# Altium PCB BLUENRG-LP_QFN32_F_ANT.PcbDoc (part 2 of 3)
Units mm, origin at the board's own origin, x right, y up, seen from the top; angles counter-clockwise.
Board outline 90.84 x 54.03 mm, 4 copper layers (Top Layer, G1 Layer, G2 Layer, Bottom Layer), stack 1.697 mm thick; 142 components, 101 nets, 450 pads, 662 vias.
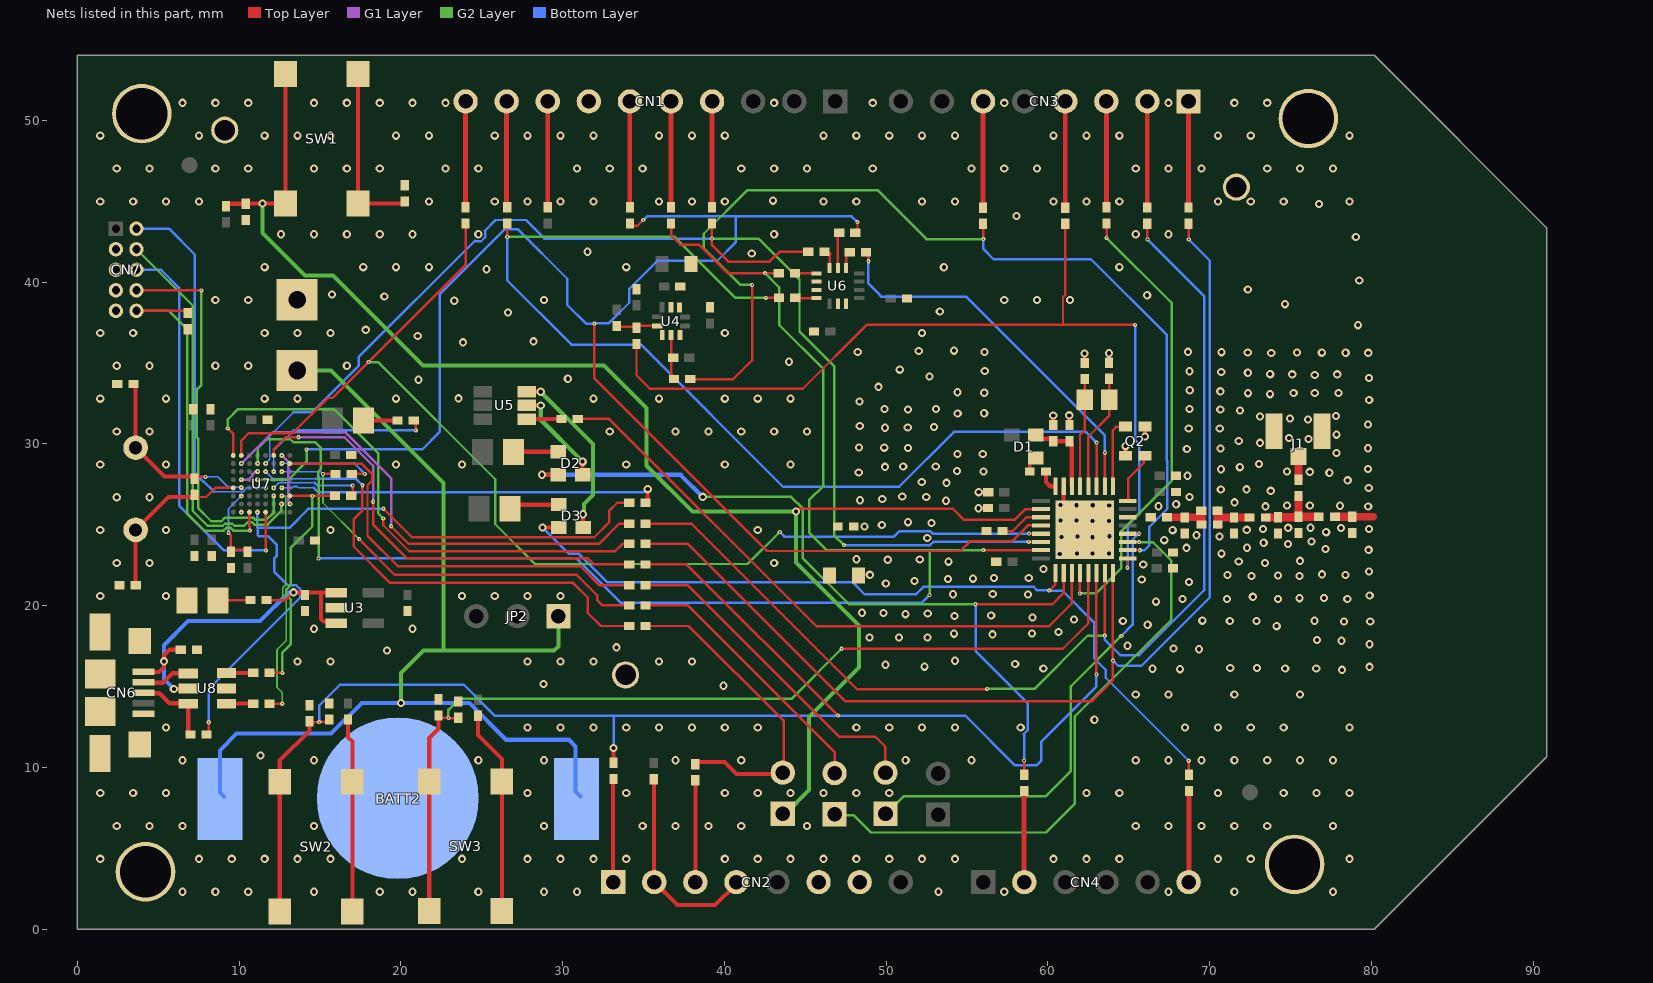
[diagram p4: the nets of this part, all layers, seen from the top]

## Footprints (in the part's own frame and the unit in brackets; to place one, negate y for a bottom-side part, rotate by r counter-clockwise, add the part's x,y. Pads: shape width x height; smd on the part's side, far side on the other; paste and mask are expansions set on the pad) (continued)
UFL_SMT [mm]
  rect 1.05x2.2 smd: 1(0.65,0.4) 3(3.6,0.4)
  rect 1x1.05 smd: 2(2.15,-1.15)
  silkscreen extent 0.1,-1.7 4.15,1.55, body extent 0.12,-1.67 4.13,1.5, height 0.76

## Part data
BATT2: library part "Battery holder_0"
C1 C2 C3 C4 C5 C6 C7 C8 C9 C10 C11 C12 C13 C14 C15 C16 C17 C19 C27 C28 C30 C31 C32 C33 C34 C35 C36 C39 C42 C43 C44: library part "MURATA GRM36"
C20 C21 C22 C23 C24 C25 C26 C29 C40 C41: library part C, PSpiceTemplate="C^@REFDES %1 %2 ?TOLERANCE[]C^@REFDES[] @VALUE ?IC/IC{}@IC/ ?TOLERANCE[]\n.model C^@REFDES CAP C{}1 DEV{}@TOLERANCE%[]"
CN6: library part "USB micro B_0"
CN7: library part CON10AP
D1 D2 D3: library part DEV3L_0
DL3 DL4: library part Diodo_led
J1: "50 Ohms, SMA Jack Receptacle, Edge Mount, .25µm Gold (Au) Plating", Manufacturer=Molex
JP1 JP3 JP4 JP5: library part Buzzer
L1 L2 L3 L4 L5 L6: library part IND_short
Q1: library part QUARZO
Q2: library part NX3225SA
R1 R2 R3 R4 R5 R6 R7 R8 R9 R13 R17 R18 R20 R22 R24 R25 R26 R27 R28 R30 R31 R32 R33 R35 R37 R38 R39 R41 R42 R43 R44 R45 R46 R47 R48 R49 R52 R53 R54 R55 R56 R57 R58 R59 R60 R61: library part R_Dup1, PSpiceTemplate="R^@REFDES %1 %2 ?TOLERANCE[]R^@REFDES[] @VALUE  ?TOLERANCE[]\n.model R^@REFDES RES R{}1 DEV{}@TOLERANCE%[]"
R29 R34 R36 R40: library part R
ST1: library part STlogo
SW1 SW2 SW3: library part SWITCH-1
TP1 TP2 TP3: library part "T POINT R"
U3: "LDLN025 Series 3.3 V 250 mA Surface Mount Fixed Ultra Low Noise LDO - SOT-23-5L", Package="SOT-23-5 STMicroelectronics"
U4: library part LPS25HB
U7: library part STM32F10XRXY, "No Description Available"
U8: library part USBUFxxW6_0
X1: library part QUARZO_Dup1

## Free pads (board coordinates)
  rect 0.254x1.092 smd: 1(60.471,22.025) 2(60.979,22.025) 3(61.487,22.025) 4(61.995,22.025) 5(62.503,22.025) 6(63.011,22.025) 7(63.519,22.027) 8(64.027,22.025) 17(64.027,27.384) 18(63.519,27.384) 19(63.011,27.384) 20(62.503,27.384) 21(61.995,27.384) 22(61.487,27.384) 23(60.979,27.384) 24(60.471,27.384)
  rect 1.092x0.254 smd: 9(64.929,22.926) 10(64.929,23.434) 11(64.929,23.942) 12(64.929,24.45) 13(64.929,24.958) 14(64.929,25.466) 15(64.929,25.974) 16(64.929,26.482) 25(59.57,26.482) 26(59.57,25.974) 27(59.57,25.466) 28(59.57,24.958) 29(59.57,24.45) 30(59.57,23.942) 31(59.57,23.434) 32(59.57,22.926)
  rect 3.607x3.607 smd: 33(62.275,24.704)

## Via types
v1: diameter 0.508, hole 0.254, Top Layer to Bottom Layer, tented both sides, 569 vias
v2: diameter 0.254, hole 0.102, Top Layer to Bottom Layer, tented both sides, 93 vias

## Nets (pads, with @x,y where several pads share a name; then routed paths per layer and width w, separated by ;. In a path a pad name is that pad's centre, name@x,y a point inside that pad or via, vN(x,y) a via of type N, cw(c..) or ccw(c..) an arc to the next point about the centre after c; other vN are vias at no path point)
BLE_RSTN: C20.2 JP5.1 pad.26 R26.2 SW1.3 SW1.4 | length 93.8
  Top Layer w0.102: R26.2@9.195,44.831 R26.2@9.212,44.848 ; C20.2@10.414,44.848 C20.2@10.422,44.856 ; SW1.4@12.866,44.856 SW1.4@12.867,44.858
  Top Layer w0.152: v1(44.422,25.822) 44.607,26.007 54.117,26.007 54.822,25.301 57.93,25.301 58.604,25.976 pad.26@59.508,25.976
  Top Layer w0.254: R26.2@9.212,44.848 C20.2@10.414,44.848 ; C20.2@10.422,44.856 v1(11.455,44.856) ; v1@11.457,44.858 11.459,44.856 SW1.4@12.866,44.856 ; SW1.4@12.867,44.858 SW1.3@12.867,52.868
  G2 Layer w0.254: v1(11.455,44.856) 11.455,43.029 14.073,40.411 15.809,40.411 21.364,34.856 32.555,34.856 35.189,32.222 35.189,28.651 38.019,25.822 v1(44.422,25.822) 44.422,22.68 48.316,18.786 48.316,16.187 45.242,13.114 45.242,8.616 JP5.1@43.675,7.048
  Bottom Layer w0.152: v1(44.422,25.822) v1@44.433,25.833
BLE_SWCLK: JP3.1 pad.12 | length 29.7
  Top Layer w0.102: pad.12@64.918,24.45 v2@65.571,24.45
  G2 Layer w0.152: JP3.1@49.949,7.074 51.084,8.209 59.855,8.209 61.417,9.771 61.417,15.021 64.519,18.123 v2(64.534,18.123)
  Bottom Layer w0.152: v2@64.534,18.138 v2(64.534,18.123) 65.241,18.83 65.241,24.079 65.608,24.445 v2(65.635,24.445)
BLE_SWDIO: JP4.1 pad.11 | length 36.6
  Top Layer w0.102: pad.11@64.985,23.937 v2@65.638,23.937
  Top Layer w0.152: pad.11@64.98,23.942 pad.11@64.985,23.937 ; v2@65.638,23.937 v2(65.643,23.933)
  G2 Layer w0.152: JP4.1@46.838,7.036 48.006,7.036 49.06,5.982 59.873,5.982 61.671,7.78 61.671,13.167 67.635,19.131 67.635,22.778 66.481,23.933 v2(65.643,23.933)
BOOT0: CN7.10 R58.2 U7.A6 | length 23.8
  Top Layer w0.152: CN7.10@3.658,38.227 R58.2@6.833,38.227 ; U7.A6@10.643,25.786 10.643,24.919 10.668,24.894 v2(10.668,24.638)
  G2 Layer w0.152: CN7.10@3.658,38.227 5.664,38.227 6.807,37.084 6.807,25.679 7.849,24.638 9.043,24.638 9.221,24.816 9.473,24.816 9.651,24.638 v2(10.668,24.638)
DM: CN6.2 U8.4 | length 2.9
  Top Layer w0.254: CN6.2@4.293,15.24 5.309,15.24 5.893,15.824 6.706,15.824 U8.4@6.853,15.677
DP: CN6.3 R43.2 U8.6 | length 4.7
  Top Layer w0.254: CN6.3@4.293,14.59 5.069,14.59 5.69,13.97 6.701,13.97 6.858,13.813 R43.2@6.858,12.04
DP-CON: R43.1 R59.2 U7.A5 | length 43.3
  Top Layer w0.152: v2@8.125,12.802 v2(8.128,12.799) R43.1@8.128,12.04 ; v2(18.92,25.997) 20.686,24.232 31.954,24.232 32.872,25.149 32.872,25.861 33.376,26.365 R59.2@33.985,26.365
  Bottom Layer w0.152: v2(8.128,12.799) 8.128,14.859 13.792,20.523 13.792,21.007 13.539,21.26 13.03,21.26 12.167,22.123 12.167,22.911 12.319,23.063 12.319,23.774 11.811,24.282 11.237,24.282 11.148,24.372 11.148,24.816 ; v2(11.125,25.781) 11.125,24.839 11.148,24.816 ; v2(18.92,25.997) 14.288,25.997 13.107,24.816 11.148,24.816
GND: BATT1.2 BATT2.3 C17.1 C19.1 C20.1 C21.1 C22.1 C23.1 C24.1 C25.1 C26.1 C27.2 C28.2 C29.2 C31.1 C32.1 C33.1 C34.1 C35.1 C36.1 C39.1 C40.1 C41.1 CN1.7 CN2.6 CN2.7 CN6.5 CN6.6 CN6.7 CN6.8 CN6.9 CN6.10 CN6.11 CN7.3 CN7.5 CN7.7 CN7.9 DL1.2 L2.1 L6.1 R28.2 R31.2 R32.2 R52.1 R58.1 TP1.1 TP2.1 TP3.1 U3.2 U4.3 U4.5 U4.8 U4.9 U6.2 U6.3 U6.6 U6.7 U7.A7 U7.B1 U7.E7 U7.F5 U7.H2 U8.2 V1.1 V2.1 V3.1 V4.1 | length 4.5
  G1 Layer w0.152: v2(10.135,27.788) 10.592,27.788 10.82,28.016 10.82,28.118 10.979,28.276 11.131,28.276 v2(11.151,28.296) ; v2(12.649,29.286) 13.03,28.905 13.03,26.429 13.157,26.302 v2(13.157,26.289)
  other v1: 6.502,2.32 8.534,2.32 10.566,2.32 14.63,2.32 18.694,2.32 20.726,2.32 24.79,2.32 28.854,2.32 30.886,2.32 53.238,2.32 57.302,2.32 67.462,2.32 71.526,2.32 77.622,2.32 1.422,4.352 7.518,4.352 9.55,4.352 11.582,4.352 13.614,4.352 15.646,4.352 23.774,4.352 27.838,4.352 29.87,4.352 31.902,4.352 33.934,4.352 40.03,4.352 42.062,4.352 44.094,4.352 46.126,4.352 48.158,4.352 50.19,4.352 52.222,4.352 54.254,4.352 60.35,4.352 62.382,4.352 64.414,4.352 70.51,4.352 72.542,4.352 78.638,4.352 2.438,6.384 4.47,6.384 6.502,6.384 14.63,6.384 28.854,6.384 34.95,6.384 36.982,6.384 39.014,6.384 41.046,6.384 45.11,6.384 65.43,6.384 67.462,6.384 69.494,6.384 71.526,6.384 73.558,6.384 77.622,6.384 1.422,8.416 3.454,8.416 5.486,8.416 27.838,8.416 33.934,8.416 40.03,8.416 42.062,8.416 44.094,8.416 46.126,8.416 48.158,8.416 50.19,8.416 62.382,8.416 64.414,8.416 70.51,8.416 74.574,8.416 76.606,8.416 78.638,8.416 6.502,10.448 14.63,10.448 24.79,10.448 28.854,10.448 36.982,10.448 41.046,10.448 51.206,10.448 55.27,10.448 65.43,10.448 67.462,10.448 69.494,10.448 71.526,10.448 73.558,10.448 75.59,10.448 77.622,10.448 11.319,10.736 5.486,12.48 27.838,12.48 29.87,12.48 31.902,12.48 33.934,12.48 35.966,12.48 37.998,12.48 40.03,12.48 42.062,12.48 48.158,12.48 50.19,12.48 52.222,12.48 54.254,12.48 58.318,12.48 68.478,12.48 70.51,12.48 72.542,12.48 74.574,12.48 78.638,12.48 62.872,12.95 65.43,14.512 67.462,14.512 71.526,14.512 75.59,14.512 39.944,15.052 28.818,15.168 13.614,16.544 15.646,16.544 27.838,16.544 29.87,16.544 31.902,16.544 35.966,16.544 37.998,16.544 19.141,17.225 33.338,17.428 14.63,18.576 20.726,18.576 1.422,20.608 5.486,20.608 23.774,20.608 25.806,20.608 27.838,20.608 29.87,20.608 2.438,22.64 4.47,22.64 43.078,22.64 1.422,24.672 5.486,24.672 15.646,24.672 42.062,24.672 2.438,26.704 4.47,26.704 1.422,28.736 5.486,28.736 19.71,28.736 23.774,28.736 33.934,28.736 40.03,28.736 44.094,28.736 2.438,30.768 4.47,30.768 32.918,30.768 36.982,30.768 39.014,30.768 41.046,30.768 43.078,30.768 45.11,30.768 1.422,32.8 5.486,32.8 11.582,32.8 13.614,32.8 19.71,32.8 31.902,32.8 35.966,32.8 40.03,32.8 42.062,32.8 44.094,32.8 23.569,32.819 21.095,33.967 30.325,34.029 2.438,34.832 4.47,34.832 8.534,34.832 10.566,34.832 16.662,34.832 44.002,35.082 23.839,36.281 28.199,36.342 21.044,36.676 1.422,36.864 3.454,36.864 11.582,36.864 13.614,36.864 15.646,36.864 40.03,36.864 52.222,36.864 17.83,37.054 79.167,37.341 26.625,38.119 53.319,38.189 74.665,38.639 23.302,38.849 8.534,38.896 10.566,38.896 28.854,38.896 57.302,38.896 59.334,38.896 61.366,38.896 18.98,39.106 66.137,39.195 15.753,39.231 72.361,39.539 79.246,40.095 25.299,40.796 11.582,40.928 17.678,40.928 19.71,40.928 21.742,40.928 33.934,40.928 53.567,40.923 64.414,40.928 41.692,41.764 31.542,41.88 79.035,42.797 12.598,42.96 14.63,42.96 16.662,42.96 18.694,42.96 20.726,42.96 24.79,42.96 43.078,42.96 65.43,42.96 67.462,42.96 58.067,44.085 76.757,44.836 1.422,44.992 3.454,44.992 5.486,44.992 7.518,44.992 21.742,44.992 25.806,44.992 27.838,44.992 29.87,44.992 31.902,44.992 35.966,44.992 37.998,44.992 40.03,44.992 46.126,44.992 48.158,44.992 52.222,44.992 54.254,44.992 60.35,44.992 62.382,44.992 64.414,44.992 70.51,44.992 72.542,44.992 74.574,44.992 78.638,44.992 43.015,45.038 2.438,47.024 4.47,47.024 8.534,47.024 10.566,47.024 14.63,47.024 16.662,47.024 18.694,47.024 22.758,47.024 24.79,47.024 30.886,47.024 32.918,47.024 34.95,47.024 41.046,47.024 43.078,47.024 45.11,47.024 49.174,47.024 55.27,47.024 57.302,47.024 59.334,47.024 65.43,47.024 67.462,47.024 69.494,47.024 73.558,47.024 75.59,47.024 77.622,47.024 1.422,49.056 7.518,49.056 11.582,49.056 13.614,49.056 15.646,49.056 19.71,49.056 21.742,49.056 25.806,49.056 27.838,49.056 29.87,49.056 31.902,49.056 35.966,49.056 37.998,49.056 40.03,49.056 46.126,49.056 48.158,49.056 50.19,49.056 52.222,49.056 54.254,49.056 60.35,49.056 62.382,49.056 64.414,49.056 70.51,49.056 72.542,49.056 78.638,49.056 6.502,51.088 8.534,51.088 10.566,51.088 14.63,51.088 16.662,51.088 18.694,51.088 20.726,51.088 22.758,51.088 43.078,51.088 49.174,51.088 57.302,51.088 67.462,51.088 71.526,51.088 73.558,51.088
  other v2: 10.135,25.781
GND_RF: C1.1 C2.1 C3.1 C4.1 C5.1 C6.1 C7.1 C8.1 C9.1 C10.1 C11.1 C12.1 C13.1 C14.1 C15.1 C42.1 C43.1 J1.1 J1.3 L2.2 L6.2 pad.23 pad.33 Q2.2 Q2.4 | length 8
  Top Layer w0.152: C3.1@60.329,31.179 C3.1@60.336,31.172 ; pad.33@60.969,26.001 pad.33@62.264,24.706 ; C4.1@61.32,31.265 61.279,31.225 C4.1@61.334,31.169 ; C2.1@62.233,35.05 C2.1@62.273,35.01 ; C1.1@63.776,35.032 C1.1@63.781,35.026
  Top Layer w0.254: v1(55.709,26.026) 55.714,26.031 56.294,26.031 C9.1@56.299,26.037 ; v1(55.723,27.017) 55.724,27.019 56.304,27.019 C8.1@56.306,27.02 ; C3.1@60.329,31.179 v1(60.329,31.759) ; pad.33@60.969,26.001 pad.23@60.969,27.386 ; C4.1@61.32,31.265 v1(61.32,31.768) ; C2.1@62.233,35.05 62.27,35.087 v1(62.27,35.585) ; C1.1@63.776,35.032 v1(63.776,35.606) ; v1(64.792,29.864) 64.792,29.287 Q2.2@64.804,29.275 ; Q2.4@66.004,31.074 66.01,31.068 v1(66.01,30.458) ; C10.1@67.916,28.027 C10.1@67.918,28.029 ; C11.1@67.919,27.029 C11.1@67.926,27.036
  other v1: 78.179,16.037 68.174,16.078 59.718,16.114 66.472,16.104 74.669,16.113 76.586,16.113 71.272,16.154 72.923,16.154 79.873,16.222 52.371,16.232 49.957,16.347 57.978,16.391 54.255,16.595 69.334,17.31 67.76,17.361 64.922,17.526 79.882,17.619 78.145,17.837 76.627,17.879 48.972,18.027 50.798,18.027 52.56,18.031 56.574,18.232 54.201,18.27 59.01,18.278 60.652,18.372 74.143,18.737 66.167,18.821 79.928,19.017 78.31,19.024 64.634,19.056 71.247,19.05 72.898,19.05 69.545,19.075 76.476,19.072 61.609,19.142 59.057,19.274 54.219,19.372 56.492,19.389 51.194,19.478 52.574,19.522 48.515,19.566 49.841,19.557 66.689,20.25 68.319,20.414 78.51,20.417 71.069,20.422 74.219,20.422 75.561,20.465 77.067,20.475 72.669,20.549 79.892,20.633 54.139,20.707 56.589,20.716 58.774,20.698 49.983,21.371 68.715,21.464 51.76,21.531 65.803,21.624 53.83,21.653 55.378,21.671 56.669,21.715 58.818,21.715 75.561,21.831 72.593,21.844 74.219,21.869 48.992,21.908 71.095,21.895 78.4,21.9 76.937,21.94 79.846,22.113 59.729,22.264 65.892,22.551 73.416,22.638 53.848,22.724 71.799,22.726 75.58,22.773 50.098,22.838 52.075,22.855 48.167,22.872 60.732,23.199 61.803,23.234 62.756,23.216 63.782,23.216 70.731,23.217 79.828,23.456 77.162,23.505 68.568,23.578 72.311,23.585 74.842,23.823 73.338,23.889 76.29,23.965 67.195,24.05 52.542,24.178 60.835,24.245 62.764,24.234 61.825,24.27 63.805,24.296 70.604,24.28 69.18,24.353 77.2,24.547 67.715,24.671 72.291,24.691 79.855,24.735 73.294,24.747 78.113,24.803 74.852,24.814 76.234,24.819 48.665,24.904 49.733,24.994 52.812,25.116 51.345,25.164 62.754,25.243 63.774,25.239 60.785,25.266 61.777,25.279 66.832,26.148 73.455,26.144 79.797,26.141 78.059,26.182 63.791,26.201 74.776,26.195 76.193,26.2 60.776,26.227 61.768,26.209 62.773,26.209 67.93,26.271 71.531,26.39 53.698,26.491 48.387,26.518 49.759,26.594 52.477,26.712 68.745,26.721 50.999,26.746 73.778,27.1 70.689,27.184 72.276,27.194 79.833,27.281 53.724,27.596 52.203,27.64 78.532,27.749 68.626,28.031 48.31,28.236 77.397,28.222 76.188,28.278 56.024,28.303 74.786,28.293 54.387,28.33 70.696,28.436 79.796,28.453 71.866,28.564 49.926,28.585 51.054,28.6 53.07,28.604 73.052,28.767 54.405,29.374 55.971,29.374 77.849,29.44 68.589,29.683 70.674,29.717 79.796,29.735 51.359,29.743 48.326,29.775 49.886,29.769 73.116,30.067 71.797,30.187 76.105,30.309 74.913,30.365 77.849,30.575 68.705,30.947 70.625,30.948 49.926,30.998 51.333,31.013 52.964,31.045 48.368,31.105 79.787,31.202 76.074,31.519 74.96,31.58 73.107,31.691 77.812,31.719 54.423,31.876 56.059,31.894 71.874,32.071 51.359,32.131 70.66,32.136 49.901,32.167 53.087,32.168 68.755,32.163 48.36,32.619 79.861,32.715 73.724,33.075 72.377,33.139 56.068,33.168 75.193,33.144 76.497,33.145 77.971,33.144 54.405,33.194 70.66,33.253 68.767,33.317 49.534,33.531 79.851,34.071 52.689,34.175 76.497,34.264 75.108,34.303 77.886,34.303 73.74,34.313 72.361,34.399 70.717,34.448 56.095,34.503 68.755,34.496 50.841,34.591 73.805,35.622 79.805,35.631 72.354,35.65 76.935,35.643 78.408,35.636 70.725,35.672 75.405,35.658 48.248,35.692 56.077,35.688 68.669,35.693 52.017,35.75 54.202,35.767
GREEN: D2.3 U5.5 | length 6.2
  Top Layer w0.254: U5.5@27.79,32.385 v1(28.651,32.385) ; D2.3@31.242,28.092 v1(31.242,28.905)
  G2 Layer w0.254: v1(28.651,32.385) 28.651,31.496 v1(31.242,28.905)
JTCK: CN7.4 U7.B2 | length 24.5
  G2 Layer w0.152: CN7.4@3.658,42.037 7.137,38.557 7.137,25.857 8.052,24.943 8.989,24.943 9.116,25.07 9.579,25.07 9.706,24.943 10.313,24.943 10.542,25.171 10.794,25.171 10.947,25.019 11.76,25.019 12.598,25.857 v2(12.598,26.289)
JTDI: CN7.8 U7.C3 | length 24
  Top Layer w0.152: CN7.8@3.658,39.497 v2(7.671,39.497)
  G2 Layer w0.152: v2(7.671,39.497) 7.671,33.655 7.391,33.376 7.391,30.4 7.468,30.324 7.468,26.035 8.28,25.222 8.909,25.222 9.112,25.425 10.899,25.425 10.999,25.326 11.708,25.326 12.149,25.767 v2(12.149,26.787)
JTDO: CN7.6 U7.A4 | length 25.4
  Top Layer w0.102: v2@11.648,23.429 v2(11.659,23.419)
  Top Layer w0.152: v2@11.648,23.429 U7.A4@11.648,25.786
  Bottom Layer w0.152: CN7.6@3.658,40.767 5.182,40.767 6.299,39.649 6.299,26.187 9.068,23.419 v2(11.659,23.419)
JTMS: CN7.2 U7.D4 | length 22.7
  Bottom Layer w0.102: 8.444,27.051 10.25,27.051 10.414,27.215 10.414,27.217 10.484,27.287 v2(11.648,27.287)
  Bottom Layer w0.152: CN7.2@3.658,43.307 5.664,43.307 7.264,41.707 7.264,28.231 7.62,27.875 7.62,27.839 7.799,27.661 7.834,27.661 8.444,27.051
NetBATT1_1: BATT1.1 BATT2.1 BATT2.2 JP2.1 | length 67.2
  G2 Layer w0.152: BATT1.1@13.589,34.544 BATT1.1@13.846,34.287
  G2 Layer w0.254: BATT1.1@13.846,34.287 14.369,34.287 14.625,34.544 15.682,34.544 22.635,27.591 22.635,17.221 ; v1(20.008,13.98) 20.008,15.835 21.394,17.221 22.635,17.221 ; JP2.1@29.743,19.406 JP2.1@29.743,19.355 29.743,17.487 29.477,17.221 22.635,17.221
  Bottom Layer w0.254: BATT2.2@9.075,8.204 8.814,8.465 8.814,11.054 9.85,12.09 15.697,12.09 17.587,13.98 v1(20.008,13.98) 24.237,13.98 26.502,11.714 30.396,11.714 30.81,11.3 30.81,8.511 BATT2.1@31.117,8.204
NetC3_2: C3.2 C4.2 D1.1 pad.22 | length 5.2
  Top Layer w0.152: D1.1@59.329,30.549 D1.1@59.253,30.549 D1.1@59.483,30.319 ; C3.2@60.189,30.319 C3.2@60.336,30.172 C3.2@60.339,30.169 ; C4.2@61.334,30.169 C4.2@61.477,30.026
  Top Layer w0.254: D1.1@59.483,30.319 C3.2@60.189,30.319 ; C3.2@60.339,30.169 C4.2@61.334,30.169 ; pad.22@61.477,27.386 C4.2@61.477,30.026
NetC5_2: C5.2 C16.2 C30.1 L1.1 | length 2.8
  Top Layer w0.254: C5.2@68.447,25.471 C5.2@68.461,25.458
  Top Layer w0.457: C30.1@67.356,25.471 C5.2@68.447,25.471 ; C5.2@68.461,25.458 69.319,25.458 69.492,25.284 69.492,25.861 C16.2@69.485,25.868 ; L1.1@69.492,25.015 L1.1@69.496,25.011
NetC6_2: C6.2 C16.1 L1.2 L5.1 | length 2.9
  Top Layer w0.508: C16.1@70.485,25.868 70.485,25.408 ; L1.2@70.496,25.011 70.489,25.011 70.485,25.015 70.485,25.408 ; L5.1@72.46,25.457 C6.2@71.496,25.457 70.534,25.457 70.485,25.408
NetC12_2: C12.2 C42.2 C44.1 L3.1 L5.2 | length 4.6
  Top Layer w0.152: C42.2@75.463,25.476 C42.2@75.489,25.502
  Top Layer w0.508: L5.2@73.46,25.457 74.223,25.457 C12.2@74.223,25.465 75.452,25.465 C42.2@75.463,25.476 ; C44.1@75.489,26.78 C42.2@75.489,25.502 L3.1@76.749,25.502
NetC17_2: C17.2 C29.1 CN6.1 R29.2 U3.1 U3.3 U8.5 | length 23.8
  Top Layer w0.102: CN6.1@4.089,15.92 4.218,16.049 4.376,16.049 CN6.1@4.524,15.9 ; v1(5.359,16.561) v1@5.376,16.577 ; v1@13.335,20.803 v1(13.36,20.828)
  Top Layer w0.152: R29.2@11.836,20.345 12.878,20.345 v1@13.335,20.803
  Top Layer w0.254: CN6.1@4.524,15.9 5.055,15.9 5.359,16.205 v1(5.359,16.561) ; v1@5.376,16.577 5.376,16.958 5.698,17.281 6.392,17.281 C29.1@6.401,17.272 ; v1(5.969,14.859) 6.778,14.859 U8.5@6.828,14.91 ; v1@13.335,20.803 14.072,20.803 14.077,20.808 15.075,20.808 ; U3.3@16.078,18.913 15.966,19.025 15.211,19.025 15.075,19.161 15.075,20.808 ; U3.1@16.078,20.813 16.073,20.808 15.075,20.808
  Bottom Layer w0.254: v1(5.969,14.859) 5.359,15.469 v1(5.359,16.561) 5.359,17.556 6.85,19.047 11.293,19.047 13.073,20.828 v1(13.36,20.828)
NetC30_2: C30.2 pad.14
NetC43_2: C43.2 L3.2 | length 2.4
  Top Layer w0.457: C43.2@78.816,25.502 80.119,25.502
  Top Layer w0.508: L3.2@77.749,25.502 C43.2@78.816,25.502
NetC44_2: C44.2 J1.2 | length 1.5
  Top Layer w0.508: C44.2@75.489,27.78 J1.2@75.489,29.235
NetCN1_4: CN1.4 R7.2 | length 6.5
  Top Layer w0.305: R7.2@39.243,44.632 CN1.4@39.243,51.171
NetCN1_5: CN1.5 R6.2 | length 6.5
  Top Layer w0.305: R6.2@36.703,44.632 CN1.5@36.703,51.171
NetCN1_6: CN1.6 R4.2 | length 6.5
  Top Layer w0.305: R4.2@34.15,44.632 34.15,51.158 CN1.6@34.163,51.171
NetCN1_8: CN1.8 R3.2 | length 6.5
  Top Layer w0.305: R3.2@29.083,44.632 CN1.8@29.083,51.171
NetCN1_9: CN1.9 R2.2 | length 6.5
  Top Layer w0.305: R2.2@26.543,44.632 CN1.9@26.543,51.171
NetCN1_10: CN1.10 R1.2 | length 6.5
  Top Layer w0.305: R1.2@24.003,44.632 CN1.10@24.003,51.171
NetCN2_1: CN2.1 R8.1 | length 6.2
  Top Layer w0.152: R8.1@33.126,9.138 R8.1@33.139,9.151
  Top Layer w0.254: CN2.1@33.126,2.916 R8.1@33.126,9.138
NetCN2_2: CN2.2 CN2.4 R5.1 | length 12.6
  Top Layer w0.254: R5.1@35.636,9.144 35.651,9.129 35.651,2.931 CN2.2@35.666,2.916 37.091,1.491 39.431,1.491 40.746,2.806 CN2.4@40.746,2.916
NetCN2_3: CN2.3 R9.1 | length 6.7
  Top Layer w0.254: CN2.3@37.8,2.916 CN2.3@38.206,2.916 R9.1@38.206,9.013 ; R9.1@38.1,9.042 R9.1@38.206,8.937
NetCN3_1: CN3.1 R24.2 | length 6.4
  Top Layer w0.305: CN3.1@68.693,51.171 68.694,51.169 68.694,44.755 R24.2@68.694,44.752
NetCN3_2: CN3.2 R22.2 | length 6.4
  Top Layer w0.305: R22.2@66.142,44.755 66.142,51.16 CN3.2@66.153,51.171
NetCN3_3: CN3.3 R20.2 | length 6.4
  Top Layer w0.152: R20.2@63.613,44.782 R20.2@63.627,44.767
  Top Layer w0.305: R20.2@63.613,44.782 CN3.3@63.613,51.171
NetCN3_4: CN3.4 R18.2 | length 6.4
  Top Layer w0.305: CN3.4@61.073,51.171 61.074,51.169 R18.2@61.074,44.742
NetCN3_6: CN3.6 R13.2 | length 6.4
  Top Layer w0.305: CN3.6@55.993,51.171 55.994,51.169 R13.2@55.994,44.742
NetCN4_2: CN4.2 R17.1 | length 5.5
  Top Layer w0.305: R17.1@58.534,8.407 58.534,2.926 CN4.2@58.544,2.916
NetCN4_6: CN4.6 R25.1 | length 5.5
  Top Layer w0.305: CN4.6@68.704,2.916 68.712,2.924 68.712,8.4 R25.1@68.72,8.407
NetD1_2: D1.2 L4.2 | length 1
  Top Layer w0.203: L4.2@58.877,28.291 58.877,28.821 59.181,29.126 D1.2@59.253,29.126
NetD2_2: D2.2 DL2.2 | length 2.8
  Top Layer w0.254: DL2.2@26.95,29.515 D2.2@29.743,29.515
NetD3_2: D3.2 DL3.2 | length 2.8
  Top Layer w0.254: DL3.2@26.949,26.238 D3.2@29.769,26.238
NetDL1_1: DL1.1 R29.1 | length 1.9
  Top Layer w0.102: DL1.1@8.695,20.326 DL1.1@8.714,20.345
  Top Layer w0.152: DL1.1@8.714,20.345 R29.1@10.566,20.345
NetDL4_2: DL4.2 R61.1 | length 1.8
  Top Layer w0.254: DL4.2@17.679,31.445 19.456,31.445
NetL4_1: L4.1 pad.24 | length 1.3
  Top Layer w0.254: L4.1@59.877,28.291 59.877,27.655 60.146,27.386 pad.24@60.461,27.386
NetQ2_1: pad.17 Q2.1 | length 4.3
  Top Layer w0.152: pad.17@64.017,27.437 64.017,30.844 64.247,31.074 Q2.1@64.804,31.074
NetQ2_3: pad.16 Q2.3 | length 3.2
  Top Layer w0.152: pad.16@64.969,26.484 64.969,27.873 65.932,28.836 65.932,29.203 Q2.3@66.004,29.275
NetR27_2: R27.2 SW2.3 SW2.4 | length 11.8
  Top Layer w0.254: R27.2@16.739,12.827 16.739,11.862 17.003,11.597 SW2.4@17.003,9.117 SW2.3@17.003,1.107
NetR28_1: R28.1 SW1.1 SW1.2 | length 10.9
  Top Layer w0.102: R28.1@20.242,44.858 R28.1@20.244,44.856
  Top Layer w0.254: SW1.1@17.357,52.868 SW1.2@17.357,44.858 R28.1@20.242,44.858
NetR30_2: R30.2 SW3.3 SW3.4 | length 12.5
  Top Layer w0.254: R30.2@24.765,13.056 24.765,12.014 26.249,10.53 SW3.4@26.249,9.142 SW3.3@26.249,1.132
NetR33_2: R33.2 R34.2 U4.2 | length 2.6
  Top Layer w0.152: R34.2@33.426,37.236 R33.2@34.493,37.236 ; R33.2@34.576,37.306 U4.2@35.846,37.306
  Top Layer w0.254: R34.2@33.35,37.16 R34.2@33.426,37.236 ; R33.2@34.493,37.236 34.569,37.313 R33.2@34.576,37.306 ; U4.2@35.846,37.306 U4.2@35.852,37.3
NetR35_2: R35.2 R36.2 U4.4 | length 2.7
  Top Layer w0.152: R36.2@36.703,35.331 U4.4@36.703,36.728 ; R35.2@36.728,34.036 R36.2@36.728,35.306
  Top Layer w0.254: R36.2@36.703,35.331 R36.2@36.728,35.306 ; R35.2@36.728,34.036 R35.2@36.754,34.011
NetR37_1: R37.1 U6.14 | length 1.1
  Top Layer w0.152: U6.14@46.509,40.874 46.509,41.749
  Top Layer w0.254: R37.1@46.32,41.876 46.382,41.876 46.509,41.749
NetR38_1: R38.1 U6.13 | length 2.2
  Top Layer w0.152: R38.1@46.961,43.053 47.017,42.997 U6.13@47.017,40.874
NetR39_1: R39.1 U6.12 | length 1
  Top Layer w0.152: U6.12@47.525,40.874 47.525,41.726 R39.1@47.621,41.823
  Top Layer w0.254: R39.1@47.621,41.823 R39.1@47.621,41.846
NetR40_1: R40.1 U5.4 | length 2
  Top Layer w0.254: U5.4@27.79,31.535 27.796,31.541 29.788,31.541 R40.1@29.794,31.547
NetR41_2: R41.2 U6.1 | length 1.2
  Top Layer w0.152: R41.2@44.502,40.55 44.508,40.544 U6.1@45.696,40.544
NetR42_2: R42.2 U6.4 | length 1.2
  Top Layer w0.152: R42.2@44.51,39.038 44.528,39.02 U6.4@45.696,39.02
NetR45_2: R45.2 U8.1 | length 1.5
  Top Layer w0.254: U8.1@9.223,13.945 R45.2@10.744,13.945
NetR46_2: R46.2 U8.3 | length 1.5
  Top Layer w0.254: U8.3@9.223,15.845 9.226,15.847 10.742,15.847 R46.2@10.744,15.85
NetR47_2: R47.2 U7.H3 | length 27.9
  Top Layer w0.152: U7.H3@12.149,29.289 12.149,29.688 12.875,30.414 v2(13.67,30.414) ; v2(18.288,26.429) 18.288,25.016 20.378,22.927 31.561,22.927 31.932,22.555 R47.2@33.985,22.555
  G1 Layer w0.152: v2(13.67,30.414) 16.525,30.414 18.288,28.651 v2(18.288,26.429)
NetR48_2: R48.2 U7.H8 | length 33.6
  Top Layer w0.152: v2(9.301,30.963) 9.652,30.612 9.652,29.299 U7.H8@9.642,29.289 ; v2(18.913,25.397) 18.913,24.974 20.523,23.364 33.247,23.364 33.708,23.825 R48.2@33.985,23.825
  G2 Layer w0.152: v2(9.301,30.963) 9.301,31.521 9.936,32.156 15.872,32.156 18.593,29.436 18.593,25.717 v2(18.913,25.397)
NetR49_1: R49.1 U7.G7 | length 29.8
  Top Layer w0.152: v2(19.403,24.915) 20.492,23.825 32.248,23.825 33.492,25.07 R49.1@33.985,25.07
  G1 Layer w0.152: v2(10.147,28.788) 12.078,30.719 16.58,30.719 19.403,27.895 v2(19.403,24.915)
NetR53_1: R53.1 U7.G1 | length 26.6
  Top Layer w0.152: U7.G1@13.15,28.788 17.566,28.788 18.24,28.115 18.24,27.747 17.94,27.447 17.94,24.318 19.818,22.44 31.099,22.44 32.279,21.26 R53.1@33.985,21.26
NetR54_2: R54.2 R55.2 U7.F2 | length 26.7
  Top Layer w0.152: v2(12.649,28.288) U7.F2@12.683,28.288 ; v2(15.189,28.143) R55.2@15.824,28.143 ; v2(17.422,24.112) 19.619,21.915 30.862,21.915 32.131,20.646 32.131,20.348 32.464,20.015 R54.2@33.985,20.015
  G2 Layer w0.102: v2(15.189,28.143) 15.189,26.345 v2(17.422,24.112)
  Bottom Layer w0.102: v2(12.649,28.288) 15.044,28.288 v2(15.189,28.143)
NetR55_1: R55.1 U7.G2 | length 6.1
  Top Layer w0.152: R55.1@17.094,28.143 v2(17.78,28.143)
  Bottom Layer w0.102: v2(12.675,28.804) 17.12,28.804
  Bottom Layer w0.152: 17.12,28.804 v2(17.78,28.143)
NetR56_2: R56.2 U7.F4 | length 29.8
  Top Layer w0.152: v2(17.625,27.445) 17.625,25.883 17.079,25.336 17.079,23.673 19.336,21.416 30.649,21.416 31.557,20.508 31.557,19.555 32.367,18.745 R56.2@33.985,18.745
  Bottom Layer w0.102: v2(11.648,28.288) 12.09,27.846 14.782,27.846
  Bottom Layer w0.152: 14.782,27.846 14.79,27.838 17.231,27.838 v2(17.625,27.445)
NetR59_1: R59.1 U7.D2 | length 23.7
  Top Layer w0.152: v1@35.255,27.192 v1(35.267,27.204)
  Top Layer w0.254: R59.1@35.255,26.365 v1@35.255,27.192
  Bottom Layer w0.102: v2(12.649,27.287) 13.288,27.287 13.372,27.371 13.603,27.371 13.687,27.287 14.622,27.287
  Bottom Layer w0.152: 14.622,27.287 14.909,27 35,27 35.204,27.204 v1(35.267,27.204)
NetR60_1: R60.1 U7.D3 | length 5.7
  Top Layer w0.152: R60.1@17.018,26.848 v2(17.018,27.432)
  Top Layer w0.254: R60.1@17.018,26.848 R60.1@17.069,26.797
  Bottom Layer w0.102: v2(12.141,27.28) 12.454,27.592 14.677,27.592
  Bottom Layer w0.152: 14.677,27.592 14.837,27.432 v2(17.018,27.432)
NetR61_2: R61.2 U7.F3 | length 11.3
  Top Layer w0.152: R61.2@20.726,31.445 20.93,31.242 v2(20.93,30.836)
  Bottom Layer w0.102: v2(12.149,28.288) 12.149,29.599 13.36,30.81
  Bottom Layer w0.152: 13.36,30.81 13.386,30.836 v2(20.93,30.836)
NRST: R52.2 R57.1 U7.C7 | length 4.8
  Top Layer w0.152: v2(9.347,24.511) 9.5,24.359 9.5,23.467 9.505,23.472 R57.1@10.546,23.472
  Bottom Layer w0.102: v2(9.347,24.511) 9.347,25.987 v2@10.14,26.779
  Bottom Layer w0.152: v2@10.14,26.779 v2@10.147,26.779
  other v2: 10.16,26.772
OSC_IN: C27.1 R44.2 U7.D8 X1.2 | length 10.6
  Top Layer w0.152: R44.2@7.239,26.721 7.976,26.721 8.541,27.286 9.646,27.286 U7.D8@9.647,27.287
  Top Layer w0.254: C27.1@3.607,21.209 X1.2@3.607,24.689 5.639,26.721 R44.2@7.239,26.721
OSC_OUT: C28.1 R44.1 U7.D7 X1.1 | length 11.5
  Top Layer w0.152: R44.1@7.239,27.991 7.264,27.965 v2(7.925,27.965)
  Top Layer w0.254: C28.1@3.607,33.706 X1.1@3.607,29.769 5.385,27.991 R44.1@7.239,27.991
  Bottom Layer w0.102: v2(7.925,27.965) 8.687,27.965 9.307,27.346 9.342,27.381 9.393,27.33 v2(10.135,27.33)
PA0: pad.9 R18.1 R33.1 | length 57
  Top Layer w0.102: v2(64.926,22.35) pad.9@64.926,22.951
  Top Layer w0.152: R33.1@34.559,36.032 34.569,36.043 34.569,34.243 35.401,33.412 44.846,33.412 48.808,37.374 60.913,37.374 ; R18.1@60.935,43.332 61.074,43.472 61.074,39.214 60.935,39.075 60.935,37.396 60.913,37.374 ; v2(65.395,37.358) 65.379,37.374 60.913,37.374
  Bottom Layer w0.152: v2@64.93,22.363 64.93,24.951 65.637,25.659 65.637,30.007 65.395,30.249 v2(65.395,37.358)
PA1: pad.10 R13.1 R35.1 | length 63.2
  Top Layer w0.102: pad.10@64.993,23.433 v2@65.646,23.433
  Top Layer w0.152: R35.1@37.889,34.011 40.551,34.011 41.715,35.175 v2(41.715,39.825) ; R13.1@55.994,43.472 56.01,43.457 v2(56.01,42.664)
  G2 Layer w0.152: v2(41.715,39.825) 41.007,39.826 38.727,42.106 38.727,42.996 41.424,45.693 49.458,45.693 52.487,42.664 v2(56.01,42.664)
  Bottom Layer w0.152: v2(56.01,42.664) 56.01,42.057 56.647,41.42 62.664,41.42 67.351,36.733 67.351,28.959 67.377,28.933 67.377,25.98 66.277,24.881 66.277,23.741 65.962,23.425 v2(65.685,23.425)
PA8: pad.8 R24.1 R48.1 | length 71.4
  Top Layer w0.152: R48.1@35.255,23.825 37.744,23.825 47.463,14.106 62.735,14.106 64.023,15.394 v2(64.023,16.607) 64.017,16.613 pad.8@64.017,22.026 ; R24.1@68.694,43.485 68.704,43.475 v2(68.704,42.642)
  Bottom Layer w0.152: v2(64.023,16.607) 64.35,16.28 65.773,16.28 70.018,20.525 70.018,41.328 v2(68.704,42.642)
PA9: pad.7 R22.1 R49.2 | length 70.2
  Top Layer w0.152: R49.2@35.255,25.07 37.973,25.07 48.204,14.839 56.221,14.839 v2(56.24,14.858) ; pad.7@63.509,22.029 63.507,22.027 63.507,18.157 v2(63.517,18.147) ; R22.1@66.142,43.485 66.154,43.472 v2(66.154,42.634)
  G2 Layer w0.152: v2(56.24,14.858) 59.178,14.858 62.467,18.147 v2(63.517,18.147)
  Bottom Layer w0.152: v2(63.517,18.147) 63.517,17.934 63.504,17.922 64.474,16.952 65.647,16.952 69.652,20.956 69.652,39.136 v2(66.154,42.634)
PA10: C40.2 pad.6 R8.2 R31.1 R47.1 SW2.1 SW2.2 | length 93.5
  Top Layer w0.102: C40.2@14.351,12.852 C40.2@14.402,12.802 ; v2(14.961,12.802) v2@14.986,12.827
  Top Layer w0.152: C40.2@14.402,12.802 v2(14.961,12.802) ; v2@14.986,12.827 R31.1@15.57,12.827 ; v1@33.139,11.195 v1(33.151,11.206) ; R47.1@35.255,22.555 37.668,22.555 v2(47.015,13.208) ; v2(62.999,15.75) 62.999,22.024 pad.6@63.001,22.026
  Top Layer w0.254: SW2.1@12.513,1.107 SW2.2@12.513,9.117 12.513,10.43 14.351,12.268 C40.2@14.351,12.852 ; R8.2@33.139,10.421 v1@33.139,11.195
  Bottom Layer w0.152: v2(14.961,12.802) 14.961,13.843 16.231,15.113 23.896,15.113 25.801,13.208 33.145,13.208 33.151,13.202 v1(33.151,11.206) ; 33.184,13.208 v2(47.015,13.208) 54.889,13.208 57.968,10.129 59.304,10.129 59.584,10.41 59.584,11.578 63.001,14.995 62.999,14.997 v2(62.999,15.75)
PA11: C41.2 pad.5 R32.1 SW3.1 SW3.2 | length 58.8
  Top Layer w0.102: v2@22.911,13.081 v2(22.936,13.056) ; C41.2@23.52,13.056 C41.2@23.546,13.081
  Top Layer w0.152: R32.1@22.327,13.081 v2@22.911,13.081 ; v2(22.936,13.056) C41.2@23.52,13.056 ; v2(47.252,17.338) 60.919,17.338 62.493,18.912 pad.5@62.493,22.026
  Top Layer w0.254: SW3.1@21.759,1.132 SW3.2@21.759,9.142 21.759,11.827 22.327,12.395 R32.1@22.327,13.081
  G2 Layer w0.152: v2(22.936,13.056) 22.936,13.564 23.635,14.262 44.176,14.262 v2(47.252,17.338)
PB0: pad.4 R20.1 | length 28.6
  Top Layer w0.152: v2(61.975,20.757) 61.975,22.017 pad.4@61.985,22.026 ; R20.1@63.627,43.497 63.635,43.49 v2(63.635,42.741)
  G2 Layer w0.152: v2(61.975,20.757) 62.974,20.757 64.523,22.307 64.523,24.592 67.647,27.715 67.647,38.728 v2(63.635,42.741)
PB1: pad.3 R40.2 | length 38.2
  Top Layer w0.152: R40.2@31.064,31.547 32.88,31.547 45.698,18.729 60.072,18.729 61.477,20.134 pad.3@61.477,22.026
PB2: D2.1 pad.2 R17.2 | length 51.8
  Top Layer w0.152: D2.1@29.742,28.094 D2.1@29.743,28.092 ; v2(55.526,20.088) 60.282,20.088 60.969,20.775 pad.2@60.969,22.026 ; v2(58.526,10.434) 58.526,10.417 58.507,10.398 58.534,10.371 R17.2@58.534,9.677
  Top Layer w0.254: v1(28.731,28.094) D2.1@29.742,28.094
  G2 Layer w0.152: v1(38.665,26.731) 44.123,26.731 44.854,26 44.854,22.929 47.694,20.088 v2(55.526,20.088)
  Bottom Layer w0.152: v2(55.526,20.088) 55.526,17.201 58.75,13.977 58.75,12.301 58.507,12.058 58.526,12.039 v2(58.526,10.434)
  Bottom Layer w0.254: v1(28.731,28.094) 37.302,28.094 v1(38.665,26.731)
PB3: D3.1 pad.1 R25.2 | length 50.9
  Top Layer w0.152: D3.1@29.765,24.837 D3.1@29.773,24.845 ; v2(60.083,20.934) 60.461,21.312 pad.1@60.461,22.026 ; v2(68.707,10.414) 68.707,9.69 R25.2@68.72,9.677
  Top Layer w0.254: v1(28.755,24.837) D3.1@29.765,24.837
  Bottom Layer w0.152: v1(28.755,24.837) 30.366,23.226 30.975,23.226 32.745,21.455 47.915,21.455 48.664,20.706 51.856,20.706 52.308,21.158 59.123,21.158 59.335,20.947 v2@60.071,20.947 ; v2(60.083,20.934) 60.885,20.934 62.855,18.964 62.855,16.754 63.576,16.033 63.576,15.545 v2(68.707,10.414)
  Bottom Layer w0.254: v2@60.071,20.947 v2(60.083,20.934)
PB4: pad.31 R6.1 R41.1 U7.G5 | length 94.8
  Top Layer w0.152: R6.1@36.703,43.497 36.703,42.888 37.272,42.319 38.435,42.319 40.197,40.557 v2(42.517,40.557) R41.1@43.233,40.557 ; v2(56.01,23.433) 59.505,23.433 pad.31@59.508,23.436
  G2 Layer w0.152: v2(11.148,28.788) 11.148,29.723 11.717,30.292 13.167,30.292 13.35,30.109 14.696,30.109 15.037,29.769 15.037,28.422 14.884,28.269 14.884,28.017 14.915,27.986 14.915,22.931 v2@14.907,22.924 ; v2(42.517,40.557) 43.388,39.686 43.388,37.366 46.126,34.628 46.126,27.409 45.242,26.525 45.242,24.516 46.325,23.433 52.723,23.433 ; v2(52.686,20.666) 52.686,23.395 52.723,23.433 ; v2(56.01,23.433) 52.723,23.433
  Bottom Layer w0.152: v2(14.91,22.921) 30.848,22.921 33.582,20.187 52.206,20.187 v2(52.686,20.666)
PB5: pad.30 R7.1 R37.2 U7.G4 | length 79.8
  Top Layer w0.152: R7.1@39.243,43.497 39.233,43.487 v2(39.233,42.692) 39.233,42.286 40.25,41.269 42.802,41.269 43.409,41.876 R37.2@45.05,41.876 ; v2(58.813,23.946) pad.30@59.558,23.945 ; pad.30@59.504,23.94 pad.30@59.508,23.944
  G2 Layer w0.152: v2(39.233,42.692) 42.107,42.692 44.645,40.154 44.645,36.952 46.787,34.81 46.787,24.343 v2(47.388,23.742)
  Bottom Layer w0.102: v2@11.648,28.798 11.895,29.045 11.895,30.488 13.36,31.953
  Bottom Layer w0.152: v2(11.648,28.788) v2@11.648,28.798 ; 13.36,31.953 14.518,31.953 17.388,34.824 17.388,35.372 24.578,42.561 24.612,42.528 24.969,42.528 25.222,42.781 25.222,43.139 25.189,43.172 25.861,43.844 27.729,43.844 28.881,42.692 v2(39.233,42.692) ; v2(47.388,23.742) 51.601,23.742 51.597,23.746 52.721,23.746 52.92,23.946 v2(58.813,23.946)
PB6: pad.29 R1.1 U7.H7 | length 71.2
  Top Layer w0.152: U7.H7@10.147,29.294 10.147,30.213 10.602,30.668 13.318,30.668 15.491,32.84 15.784,32.84 v2(18.004,35.06) 24.003,41.059 R1.1@24.003,43.497 ; v2(58.829,24.459) 58.832,24.455 59.556,24.455 pad.29@59.559,24.452
  G2 Layer w0.152: v2(18.004,35.06) 18.599,35.06 25.839,27.82 25.839,25.037 28.298,22.578 41.439,22.578 v2(43.422,24.561)
  Bottom Layer w0.152: v2(43.422,24.561) 43.712,24.27 50.483,24.27 50.823,24.61 52.721,24.61 52.879,24.452 52.885,24.459 v2(58.829,24.459)
PB7: pad.28 R4.1 R38.2 U7.E5 | length 100
  Top Layer w0.152: v2(31.961,37.438) 31.961,34.046 42.624,23.383 54.584,23.383 55.181,23.981 57.785,23.981 58.765,24.96 pad.28@59.508,24.96 ; R4.1@34.163,43.497 34.648,43.497 v2(34.986,43.835) ; v2(48.225,43.708) 48.231,43.702 R38.2@48.231,43.053
  G2 Layer w0.152: v2@11.153,27.783 v2(11.148,27.788) 13.057,27.788 14.175,28.906 14.175,29.659 v2@14.171,29.664
  Bottom Layer w0.152: v2(14.164,29.667) 21.328,29.667 22.402,30.741 22.402,39.249 26.415,43.263 27.232,43.263 30.285,40.21 30.285,38.6 31.447,37.438 v2(31.961,37.438) 31.98,37.457 32.052,37.457 32.065,37.471 32.867,37.471 34.123,38.727 34.123,39.587 35.861,41.326 39.562,41.326 40.699,42.463 40.699,44.02 ; v2(34.986,43.835) 35.222,44.072 47.862,44.072 v2(48.225,43.708)
PB12: C2.2 pad.21 Q1.1 | length 6.7
  Top Layer w0.152: pad.21@61.985,27.386 61.985,30.546 62.277,30.838 Q1.1@62.277,32.731 62.277,34.006 C2.2@62.273,34.01
PB13: C1.2 pad.20 Q1.2 | length 7.1
  Top Layer w0.152: pad.20@62.493,27.437 62.493,30.444 63.801,31.752 Q1.2@63.801,32.731 63.801,34.007 C1.2@63.781,34.026
PB14: pad.19 R2.1 R42.1 | length 67.7
  Top Layer w0.152: v2(26.576,42.794) 26.576,43.492 R2.1@26.581,43.497 ; v2(42.583,39.034) 42.587,39.038 R42.1@43.24,39.038 ; pad.19@63.001,27.437 63.009,27.444 v2(63.009,30.082)
  G2 Layer w0.152: v2(26.576,42.794) 36.927,42.794 40.687,39.034 v2(42.583,39.034)
  Bottom Layer w0.152: v2(26.576,42.794) 26.576,40.113 30.545,36.144 34.844,36.144 43.631,27.357 50.803,27.357 54.188,30.742 62.349,30.742 v2(63.009,30.082)
PB15: pad.18 R39.2 | length 23.6
  Top Layer w0.152: R39.2@48.891,41.846 48.899,41.839 v2(48.899,41.293) ; pad.18@63.509,27.437 63.526,27.454 v2(63.526,29.454)
  Bottom Layer w0.152: v2(48.899,41.293) 48.899,39.921 49.65,39.17 49.65,39.146 49.685,39.111 54.946,39.111 63.526,30.53 v2(63.526,29.454)
RED: D3.3 U5.6 | length 10.9
  Top Layer w0.152: U5.6@27.79,33.235 U5.6@27.802,33.223
  Top Layer w0.254: U5.6@27.802,33.223 v1(28.651,33.223) ; D3.3@31.267,24.816 v1(31.267,25.654)
  G2 Layer w0.254: v1(28.651,33.223) 31.877,29.997 31.877,26.848 31.316,26.287 31.316,25.703 v1(31.267,25.654)
RSTN: JP5.2 R9.2 R56.1 | length 19.9
  Top Layer w0.152: R56.1@35.255,18.745 37.795,18.745 43.675,12.865 JP5.2@43.675,9.588
  Top Layer w0.254: R9.2@38.202,10.338 40.002,10.338 40.752,9.588 JP5.2@43.675,9.588
SWCLK: JP3.2 R53.2 | length 20.5
  Top Layer w0.152: R53.2@35.255,21.26 37.744,21.26 47.092,11.913 49.327,11.913 49.949,11.29 JP3.2@49.949,9.614
  G1 Layer w0.254: JP3.2@49.936,9.614 JP3.2@49.949,9.614
SWDIO: JP4.2 R54.1 | length 16.7
  Top Layer w0.152: R54.1@35.255,20.015 37.744,20.015 46.838,10.922 JP4.2@46.838,9.576
USBDM: R46.1 R60.2 U7.C1 | length 15.3
  Top Layer w0.102: v2@14.521,26.787 v2(14.524,26.784) v2@14.536,26.797
  Top Layer w0.152: R46.1@12.014,15.85 12.017,15.847 v2(12.675,15.847) ; U7.C1@13.144,26.787 v2@14.521,26.787 ; v2@14.536,26.797 R60.2@15.799,26.797 ; R60.2@15.921,26.792 R60.2@15.926,26.797
  G2 Layer w0.152: v2(12.675,15.847) 12.675,17.104 13.208,17.638 13.208,20.37 12.929,20.649 12.929,21.007 13.208,21.286 13.208,23.589 14.524,24.905 v2(14.524,26.784)
USBDP: R45.1 U7.C2 | length 14.3
  Top Layer w0.152: R45.1@12.014,13.945 12.017,13.942 v2(12.67,13.942)
  G2 Layer w0.102: v2(12.644,26.787) 12.878,26.787 12.878,25.909 12.87,25.902 12.87,25.67 12.89,25.65 12.89,21.292 12.7,21.102 12.7,20.554 12.929,20.326 12.929,17.866 12.342,17.28 12.342,14.968 12.67,14.641 v2(12.67,13.942)
VCAP: C7.2 pad.27 | length 2.7
  Top Layer w0.152: C7.2@57.2,24.617 57.825,24.617 58.676,25.468 pad.27@59.508,25.468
